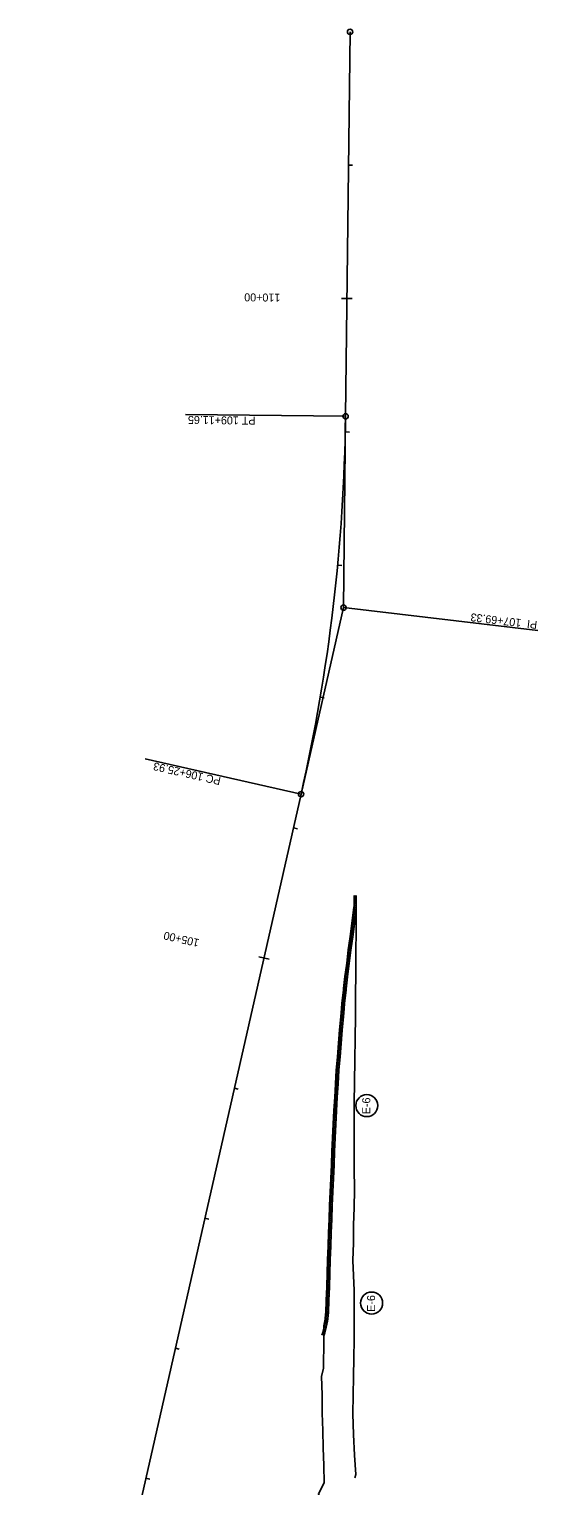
# Model space of a CAD drawing. Extents: x 1710760 to 1712722, y 548603 to 551099.
# Drawn here: x 1712247 to 1712628, y 550007 to 551099 of the extents above; entities that cross this region are included whole.
import ezdxf

# ---------------------------------------------------------------- set-up
doc = ezdxf.new("R2010")
doc.units = 0
for name, color, linetype in [('R_Draft', 7, 'Continuous'), ('R_Erosion', 7, 'Continuous'), ('R_Horz Alg', 7, 'Continuous'), ('R_Horz Alg Annot', 7, 'Continuous')]:
    doc.layers.add(name, color=color, linetype=linetype)

msp = doc.modelspace()

# ---------------------------------------------------------------- linework, layer by layer
at = {"layer": 'R_Draft'}
for points in [[(1712492.2, 550449.8), (1712491.6, 550449), (1712490.2, 550439), (1712488.8, 550429.1), (1712487.5, 550419.1), (1712486.2, 550409.2), (1712485, 550399.2), (1712483.7, 550389.2), (1712482.7, 550380.1), (1712482.6, 550379.2), (1712481.4, 550369.2), (1712481, 550365.2), (1712480.5, 550359.2), (1712479.6, 550349.1), (1712478.8, 550339.1), (1712478, 550329), (1712477.2, 550318.9), (1712476.6, 550308.8), (1712476, 550298.7), (1712475.4, 550288.6), (1712474.9, 550278.4), (1712474.4, 550268.3), (1712473.9, 550258.1), (1712473.5, 550248), (1712473.1, 550237.8), (1712472.7, 550227.6), (1712472.2, 550217.5), (1712471.8, 550207.3), (1712471.4, 550197.2), (1712471, 550187), (1712470.7, 550176.8), (1712470.4, 550166.7), (1712470, 550156.5), (1712469.7, 550146.3), (1712469.3, 550137.3)], [(1712491, 550013.2), (1712491.9, 550015.8), (1712490.8, 550030.2), (1712490.2, 550045.8), (1712489.5, 550061.4), (1712489.8, 550075.3), (1712490, 550089.2), (1712490.3, 550103.1), (1712490.5, 550117), (1712490.5, 550135.4), (1712490.5, 550153.8), (1712489.7, 550176.3), (1712490, 550189.5), (1712490.2, 550202.8), (1712490.5, 550216), (1712490.8, 550229.3), (1712490.7, 550245.5), (1712490.7, 550261.6), (1712490.7, 550277.8), (1712490.7, 550293.9), (1712490.9, 550310.2), (1712491.1, 550326.5), (1712491.3, 550342.9), (1712491.5, 550359.2), (1712491.6, 550375.2), (1712491.8, 550391.3), (1712491.9, 550407.3), (1712492, 550423.4), (1712492.1, 550439.2), (1712492.2, 550449.8)], [(1712467.8, 550127.2), (1712467.8, 550116.5), (1712467.5, 550095.6), (1712466.2, 550089.2), (1712466.5, 550075.5), (1712466.7, 550061.9), (1712467.1, 550048.8), (1712467.4, 550035.7), (1712467.8, 550022.6), (1712468.1, 550009.5), (1712463.8, 550001.4), (1712464.3, 549999.7)]]:
    msp.add_lwpolyline(points, dxfattribs=at)
msp.add_arc((1712395.3, 550143.5), 74.3, 347.3834, 355.2233, dxfattribs=at)
at = {"layer": 'R_Erosion'}
for p, q in [((1712492.1, 550447.2), (1712490.6, 550448.7)), ((1712492.1, 550448.6), (1712490.9, 550449.8)), ((1712491.8, 550436.2), (1712490.5, 550437.5)), ((1712492.1, 550445.8), (1712490.6, 550447.3)), ((1712492.1, 550444.4), (1712490.6, 550445.9)), ((1712492.1, 550443), (1712490.6, 550444.5)), ((1712492.1, 550441.6), (1712490.6, 550443)), ((1712492.1, 550440.1), (1712490.6, 550441.6)), ((1712492.1, 550438.7), (1712490.6, 550440.2)), ((1712492, 550437.5), (1712490.6, 550438.8)), ((1712490.3, 550425), (1712489, 550426.3)), ((1712490.5, 550426.2), (1712489.1, 550427.6)), ((1712490.6, 550427.5), (1712489.3, 550428.8)), ((1712490.8, 550428.7), (1712489.5, 550430.1)), ((1712491, 550430), (1712489.6, 550431.3)), ((1712491.1, 550431.2), (1712489.8, 550432.6)), ((1712491.3, 550432.5), (1712490, 550433.8)), ((1712491.5, 550433.7), (1712490.1, 550435.1)), ((1712491.6, 550435), (1712490.3, 550436.3)), ((1712489, 550415), (1712487.7, 550416.3)), ((1712489.2, 550416.2), (1712487.8, 550417.6)), ((1712489.3, 550417.5), (1712488, 550418.8)), ((1712489.5, 550418.7), (1712488.1, 550420.1)), ((1712489.6, 550420), (1712488.3, 550421.3)), ((1712489.8, 550421.2), (1712488.5, 550422.6)), ((1712490, 550422.5), (1712488.6, 550423.8)), ((1712490.1, 550423.7), (1712488.8, 550425.1)), ((1712487.5, 550403.7), (1712486.2, 550405)), ((1712487.7, 550405), (1712486.4, 550406.3)), ((1712487.9, 550406.2), (1712486.5, 550407.5)), ((1712488, 550407.5), (1712486.7, 550408.8)), ((1712488.2, 550408.7), (1712486.8, 550410.1)), ((1712488.3, 550410), (1712487, 550411.3)), ((1712488.5, 550411.2), (1712487.2, 550412.6)), ((1712488.7, 550412.5), (1712487.3, 550413.8)), ((1712488.8, 550413.7), (1712487.5, 550415.1)), ((1712486.1, 550392.4), (1712484.8, 550393.7)), ((1712486.3, 550393.6), (1712485, 550395)), ((1712486.5, 550394.9), (1712485.1, 550396.2)), ((1712486.6, 550396.2), (1712485.3, 550397.5)), ((1712486.8, 550397.4), (1712485.4, 550398.8)), ((1712486.9, 550398.7), (1712485.6, 550400)), ((1712487.1, 550399.9), (1712485.7, 550401.3)), ((1712487.2, 550401.2), (1712485.9, 550402.5)), ((1712487.4, 550402.4), (1712486, 550403.8)), ((1712484.9, 550382.3), (1712483.6, 550383.6)), ((1712485.1, 550383.5), (1712483.7, 550384.9)), ((1712485.2, 550384.8), (1712483.9, 550386.1)), ((1712485.4, 550386.1), (1712484, 550387.4)), ((1712485.5, 550387.3), (1712484.2, 550388.7)), ((1712485.7, 550388.6), (1712484.3, 550389.9)), ((1712485.8, 550389.8), (1712484.5, 550391.2)), ((1712486, 550391.1), (1712484.6, 550392.5)), ((1712483.6, 550370.8), (1712482.3, 550372.2)), ((1712483.8, 550372.1), (1712482.4, 550373.5)), ((1712483.9, 550373.4), (1712482.6, 550374.7)), ((1712484.1, 550374.7), (1712482.7, 550376)), ((1712484.2, 550375.9), (1712482.9, 550377.3)), ((1712484.4, 550377.2), (1712483, 550378.6)), ((1712484.5, 550378.5), (1712483.1, 550379.8)), ((1712484.6, 550379.7), (1712483.3, 550381.1)), ((1712484.8, 550381), (1712483.4, 550382.3)), ((1712482.6, 550360.5), (1712481.2, 550361.9)), ((1712482.7, 550361.8), (1712481.3, 550363.2)), ((1712482.8, 550363.2), (1712481.4, 550364.5)), ((1712482.9, 550364.5), (1712481.6, 550365.8)), ((1712483.1, 550365.7), (1712481.7, 550367.1)), ((1712483.2, 550367), (1712481.8, 550368.4)), ((1712483.3, 550368.3), (1712482, 550369.7)), ((1712483.5, 550369.6), (1712482.1, 550370.9)), ((1712481.6, 550348.8), (1712480.2, 550350.2)), ((1712481.7, 550350.1), (1712480.3, 550351.5)), ((1712481.8, 550351.4), (1712480.4, 550352.8)), ((1712481.9, 550352.7), (1712480.6, 550354.1)), ((1712482.1, 550354), (1712480.7, 550355.4)), ((1712482.2, 550355.3), (1712480.8, 550356.7)), ((1712482.3, 550356.6), (1712480.9, 550358)), ((1712482.4, 550357.9), (1712481, 550359.3)), ((1712482.5, 550359.2), (1712481.1, 550360.6)), ((1712480.7, 550338.4), (1712479.3, 550339.8)), ((1712480.8, 550339.7), (1712479.4, 550341.1)), ((1712480.9, 550341), (1712479.5, 550342.4)), ((1712481, 550342.3), (1712479.7, 550343.7)), ((1712481.2, 550343.6), (1712479.8, 550345)), ((1712481.3, 550344.9), (1712479.9, 550346.3)), ((1712481.4, 550346.2), (1712480, 550347.6)), ((1712481.5, 550347.5), (1712480.1, 550348.9)), ((1712479.8, 550326.6), (1712478.4, 550328)), ((1712479.9, 550327.9), (1712478.5, 550329.3)), ((1712480, 550329.2), (1712478.6, 550330.6)), ((1712480.1, 550330.5), (1712478.7, 550331.9)), ((1712480.2, 550331.8), (1712478.8, 550333.2)), ((1712480.3, 550333.2), (1712478.9, 550334.6)), ((1712480.4, 550334.5), (1712479, 550335.9)), ((1712480.5, 550335.8), (1712479.1, 550337.2)), ((1712480.6, 550337.1), (1712479.2, 550338.5)), ((1712479.1, 550317.3), (1712477.7, 550318.8)), ((1712479.1, 550316), (1712477.7, 550317.4)), ((1712479.2, 550318.7), (1712477.8, 550320.1)), ((1712479.3, 550320), (1712477.9, 550321.4)), ((1712479.4, 550321.3), (1712478, 550322.7)), ((1712479.5, 550322.6), (1712478.1, 550324)), ((1712479.6, 550323.9), (1712478.2, 550325.3)), ((1712479.7, 550325.3), (1712478.3, 550326.7)), ((1712478.4, 550305.4), (1712477, 550306.8)), ((1712478.6, 550308), (1712477.1, 550309.5)), ((1712478.5, 550306.7), (1712477.1, 550308.1)), ((1712478.6, 550309.4), (1712477.2, 550310.8)), ((1712478.7, 550310.7), (1712477.3, 550312.1)), ((1712478.8, 550312), (1712477.4, 550313.4)), ((1712478.9, 550313.4), (1712477.5, 550314.8)), ((1712479, 550314.7), (1712477.6, 550316.1)), ((1712477.7, 550294.7), (1712476.3, 550296.1)), ((1712477.8, 550296), (1712476.4, 550297.5)), ((1712478, 550298.7), (1712476.5, 550300.1)), ((1712477.9, 550297.4), (1712476.5, 550298.8)), ((1712478, 550300.1), (1712476.6, 550301.5)), ((1712478.1, 550301.4), (1712476.7, 550302.8)), ((1712478.2, 550302.7), (1712476.8, 550304.1)), ((1712478.3, 550304.1), (1712476.9, 550305.5)), ((1712477.2, 550284), (1712475.7, 550285.4)), ((1712477.2, 550285.3), (1712475.8, 550286.7)), ((1712477.3, 550286.7), (1712475.9, 550288.1)), ((1712477.5, 550289.3), (1712476, 550290.8)), ((1712477.4, 550288), (1712476, 550289.4)), ((1712477.5, 550290.7), (1712476.1, 550292.1)), ((1712477.7, 550293.4), (1712476.2, 550294.8)), ((1712477.6, 550292), (1712476.2, 550293.4)), ((1712476.6, 550273.2), (1712475.2, 550274.6)), ((1712476.7, 550275.9), (1712475.3, 550277.3)), ((1712476.7, 550274.6), (1712475.3, 550276)), ((1712476.8, 550277.3), (1712475.4, 550278.7)), ((1712477, 550279.9), (1712475.5, 550281.4)), ((1712476.9, 550278.6), (1712475.5, 550280)), ((1712477, 550281.3), (1712475.6, 550282.7)), ((1712477.1, 550282.6), (1712475.7, 550284.1)), ((1712476, 550261), (1712474.6, 550262.5)), ((1712476.2, 550263.8), (1712474.7, 550265.2)), ((1712476.1, 550262.4), (1712474.7, 550263.8)), ((1712476.2, 550265.1), (1712474.8, 550266.5)), ((1712476.4, 550267.8), (1712474.9, 550269.2)), ((1712476.3, 550266.5), (1712474.9, 550267.9)), ((1712476.4, 550269.2), (1712475, 550270.6)), ((1712476.6, 550271.9), (1712475.1, 550273.3)), ((1712476.5, 550270.5), (1712475.1, 550271.9)), ((1712475.6, 550250.2), (1712474.1, 550251.6)), ((1712475.7, 550252.9), (1712474.2, 550254.4)), ((1712475.6, 550251.6), (1712474.2, 550253)), ((1712475.7, 550254.3), (1712474.3, 550255.7)), ((1712475.9, 550257), (1712474.4, 550258.4)), ((1712475.8, 550255.6), (1712474.4, 550257.1)), ((1712476, 550259.7), (1712474.5, 550261.1)), ((1712475.9, 550258.3), (1712474.5, 550259.8)), ((1712475.2, 550240.7), (1712473.7, 550242.1)), ((1712475.1, 550239.3), (1712473.7, 550240.8)), ((1712475.2, 550242), (1712473.8, 550243.5)), ((1712475.4, 550244.8), (1712473.9, 550246.2)), ((1712475.3, 550243.4), (1712473.9, 550244.9)), ((1712475.5, 550247.5), (1712474, 550248.9)), ((1712475.4, 550246.1), (1712474, 550247.6)), ((1712475.5, 550248.8), (1712474.1, 550250.3)), ((1712474.8, 550229.8), (1712473.3, 550231.2)), ((1712474.7, 550228.4), (1712473.3, 550229.9)), ((1712474.9, 550232.5), (1712473.4, 550234)), ((1712474.8, 550231.1), (1712473.4, 550232.6)), ((1712475, 550235.2), (1712473.5, 550236.7)), ((1712474.9, 550233.9), (1712473.5, 550235.3)), ((1712475.1, 550238), (1712473.6, 550239.4)), ((1712475, 550236.6), (1712473.6, 550238.1)), ((1712474.2, 550217.6), (1712472.8, 550219)), ((1712474.4, 550220.3), (1712472.9, 550221.7)), ((1712474.3, 550219), (1712472.9, 550220.4)), ((1712474.4, 550221.7), (1712473, 550223.1)), ((1712474.6, 550224.3), (1712473.1, 550225.8)), ((1712474.5, 550223), (1712473.1, 550224.4)), ((1712474.7, 550227), (1712473.2, 550228.5)), ((1712474.6, 550225.7), (1712473.2, 550227.1)), ((1712473.8, 550206.8), (1712472.3, 550208.2)), ((1712473.9, 550209.5), (1712472.4, 550210.9)), ((1712473.8, 550208.1), (1712472.4, 550209.6)), ((1712473.9, 550210.8), (1712472.5, 550212.3)), ((1712474.1, 550213.5), (1712472.6, 550215)), ((1712474, 550212.2), (1712472.6, 550213.6)), ((1712474.2, 550216.2), (1712472.7, 550217.7)), ((1712474.1, 550214.9), (1712472.7, 550216.3)), ((1712473.4, 550197.3), (1712471.9, 550198.7)), ((1712473.3, 550195.9), (1712471.9, 550197.4)), ((1712473.5, 550200), (1712472, 550201.4)), ((1712473.4, 550198.6), (1712472, 550200.1)), ((1712473.6, 550202.7), (1712472.1, 550204.1)), ((1712473.5, 550201.3), (1712472.1, 550202.8)), ((1712473.6, 550204.1), (1712472.2, 550205.5)), ((1712473.7, 550205.4), (1712472.3, 550206.8)), ((1712473, 550186.3), (1712471.5, 550187.8)), ((1712472.9, 550185), (1712471.5, 550186.4)), ((1712473.1, 550189.1), (1712471.6, 550190.5)), ((1712473, 550187.7), (1712471.6, 550189.2)), ((1712473.2, 550191.8), (1712471.7, 550193.3)), ((1712473.1, 550190.4), (1712471.7, 550191.9)), ((1712473.3, 550194.5), (1712471.8, 550196)), ((1712473.2, 550193.2), (1712471.8, 550194.6)), ((1712472.6, 550174), (1712471.1, 550175.5)), ((1712472.7, 550178.1), (1712471.2, 550179.6)), ((1712472.7, 550176.8), (1712471.2, 550178.2)), ((1712472.6, 550175.4), (1712471.2, 550176.8)), ((1712472.8, 550180.9), (1712471.3, 550182.3)), ((1712472.7, 550179.5), (1712471.3, 550180.9)), ((1712472.9, 550183.6), (1712471.4, 550185.1)), ((1712472.8, 550182.2), (1712471.4, 550183.7)), ((1712472.3, 550164.4), (1712470.8, 550165.9)), ((1712472.2, 550163), (1712470.8, 550164.5)), ((1712472.4, 550167.1), (1712470.9, 550168.6)), ((1712472.3, 550165.8), (1712470.9, 550167.2)), ((1712472.5, 550171.3), (1712471, 550172.7)), ((1712472.5, 550169.9), (1712471, 550171.3)), ((1712472.4, 550168.5), (1712471, 550170)), ((1712472.5, 550172.6), (1712471.1, 550174.1)), ((1712471.9, 550152.1), (1712470.4, 550153.5)), ((1712472, 550154.8), (1712470.5, 550156.3)), ((1712471.9, 550153.4), (1712470.5, 550154.9)), ((1712472.1, 550157.5), (1712470.6, 550159)), ((1712472, 550156.2), (1712470.6, 550157.6)), ((1712472.2, 550161.7), (1712470.7, 550163.1)), ((1712472.2, 550160.3), (1712470.7, 550161.7)), ((1712472.1, 550158.9), (1712470.7, 550160.4)), ((1712471.5, 550141.2), (1712470, 550142.6)), ((1712471.6, 550143.9), (1712470.1, 550145.3)), ((1712471.5, 550142.5), (1712470.1, 550144)), ((1712471.7, 550146.6), (1712470.2, 550148.1)), ((1712471.6, 550145.2), (1712470.2, 550146.7)), ((1712471.8, 550149.3), (1712470.3, 550150.8)), ((1712471.7, 550148), (1712470.3, 550149.4)), ((1712471.8, 550150.7), (1712470.4, 550152.2)), ((1712470.5, 550130.8), (1712469.2, 550132.1)), ((1712470.7, 550132), (1712469.4, 550133.3)), ((1712470.9, 550133.3), (1712469.6, 550134.6)), ((1712471.1, 550134.5), (1712469.7, 550135.9)), ((1712471.2, 550135.8), (1712469.8, 550137.2)), ((1712471.4, 550138.4), (1712469.9, 550139.9)), ((1712471.3, 550137.1), (1712469.9, 550138.5)), ((1712471.4, 550139.8), (1712470, 550141.2)), ((1712468.1, 550120.5), (1712466.9, 550121.7)), ((1712468.4, 550121.6), (1712467.2, 550122.8)), ((1712468.7, 550122.7), (1712467.5, 550123.9)), ((1712469, 550123.8), (1712467.8, 550125.1)), ((1712469.3, 550125), (1712468.1, 550126.2)), ((1712469.6, 550126.1), (1712468.3, 550127.3)), ((1712469.8, 550127.2), (1712468.6, 550128.5)), ((1712470.1, 550128.4), (1712468.8, 550129.7)), ((1712470.3, 550129.6), (1712469, 550130.9))]:
    msp.add_line(p, q, dxfattribs=at)
for points in [[(1712490.7, 550449.8), (1712490.6, 550438.6), (1712488, 550419.1), (1712486.7, 550409.1), (1712485.5, 550399.1), (1712484.2, 550389.1), (1712483.2, 550380), (1712483.1, 550379.2), (1712481.9, 550369.2), (1712481.5, 550365.1), (1712481, 550359.1), (1712480.1, 550349.1), (1712479.3, 550339), (1712478.5, 550329), (1712477.7, 550318.9), (1712477.1, 550308.8), (1712476.5, 550298.7), (1712475.9, 550288.5), (1712475.4, 550278.4), (1712474.9, 550268.3), (1712474.4, 550258.1), (1712474, 550248), (1712473.6, 550237.8), (1712473.2, 550227.6), (1712472.7, 550217.5), (1712472.3, 550207.3), (1712471.9, 550197.2), (1712471.5, 550187), (1712471.2, 550176.8), (1712470.9, 550166.6), (1712470.5, 550156.5), (1712470.2, 550146.3), (1712469.8, 550137.3), (1712469.8, 550137.2)], [(1712471.3, 550137.1), (1712471.3, 550137.2), (1712471.7, 550146.2), (1712472, 550156.4), (1712472.4, 550166.6), (1712472.7, 550176.8), (1712473, 550186.9), (1712473.4, 550197.1), (1712473.8, 550207.3), (1712474.2, 550217.4), (1712474.7, 550227.6), (1712475.1, 550237.7), (1712475.5, 550247.9), (1712475.9, 550258), (1712476.4, 550268.2), (1712476.9, 550278.3), (1712477.4, 550288.4), (1712477.9, 550298.6), (1712478.6, 550308.7), (1712479.2, 550318.8), (1712480, 550328.8), (1712480.8, 550338.9), (1712481.6, 550349), (1712482.5, 550359), (1712483, 550365), (1712483.4, 550369), (1712484.6, 550379), (1712484.7, 550379.8), (1712485.7, 550389), (1712486.9, 550398.9), (1712488.2, 550408.9), (1712489.5, 550418.9), (1712492.1, 550438.5), (1712492.2, 550449.8)]]:
    msp.add_lwpolyline(points, dxfattribs=at)
for centre in [(1712500.1, 550292.4), (1712503.7, 550144.3)]:
    msp.add_circle(centre, 8.26, dxfattribs=at)
for radius in [74.8, 76.3]:
    msp.add_arc((1712395.3, 550143.5), radius, 341.9394, 355.2233, dxfattribs=at)
at = {"layer": 'R_Horz Alg'}
for p, q in [((1712484.2, 550809.1), (1712487.5, 551097.3)), ((1712246.8, 549627.3), (1712450.8, 550525.8))]:
    msp.add_line(p, q, dxfattribs=at)
msp.add_arc((1711136.1, 550824.3), 1348.1, 347.2066, 359.3498, dxfattribs=at)
at = {"layer": 'R_Horz Alg Annot'}
for p, q in [((1712482.6, 550665.7), (1712484.2, 550809.1)), ((1712450.8, 550525.8), (1712482.6, 550665.7))]:
    msp.add_line(p, q, dxfattribs=at)
for points in [[(1712489.3, 550997.4), (1712486.3, 550997.4)], [(1712481.2, 550897.4), (1712489.2, 550897.3)], [(1712484.2, 550809.1), (1712364.2, 550810.4)], [(1712487, 550797.3), (1712484, 550797.4)], [(1712481.3, 550697.3), (1712478.3, 550697.6)], [(1712482.6, 550665.7), (1712628.4, 550648.5)], [(1712468.2, 550598), (1712465.2, 550598.5)], [(1712450.8, 550525.8), (1712333.8, 550552.4)], [(1712448, 550499.9), (1712445.1, 550500.5)], [(1712419, 550403.9), (1712426.8, 550402.1)], [(1712403.7, 550304.8), (1712400.8, 550305.5)], [(1712381.6, 550207.3), (1712378.6, 550208)], [(1712359.4, 550109.8), (1712356.5, 550110.5)], [(1712337.3, 550012.3), (1712334.3, 550013)]]:
    msp.add_lwpolyline(points, dxfattribs=at)
for centre in [(1712487.5, 551097.3), (1712484.2, 550809.1), (1712482.6, 550665.7), (1712450.8, 550525.8)]:
    msp.add_circle(centre, 2, dxfattribs=at)

# ---------------------------------------------------------------- texts
at = {"layer": 'R_Erosion'}
for p in [(1712502.7, 550285.9), (1712506.3, 550137.8)]:
    msp.add_text('E-6 ', height=6, rotation=90, dxfattribs=at).set_placement(p)
at = {"layer": 'R_Horz Alg Annot'}
for s, rotation, p in [('110+00', 179.3498, (1712435.2, 550901)), ('PT 109+11.65', 179.3498, (1712416.6, 550808.8)), ('PI  107+69.33', 173.2782, (1712628.2, 550655.6)), ('PC 106+25.93', 167.2066, (1712391, 550538.4)), ('105+00', 167.2066, (1712374.8, 550417))]:
    msp.add_text(s, height=6, rotation=rotation, dxfattribs=at).set_placement(p)

doc.saveas('drawing.dxf')
